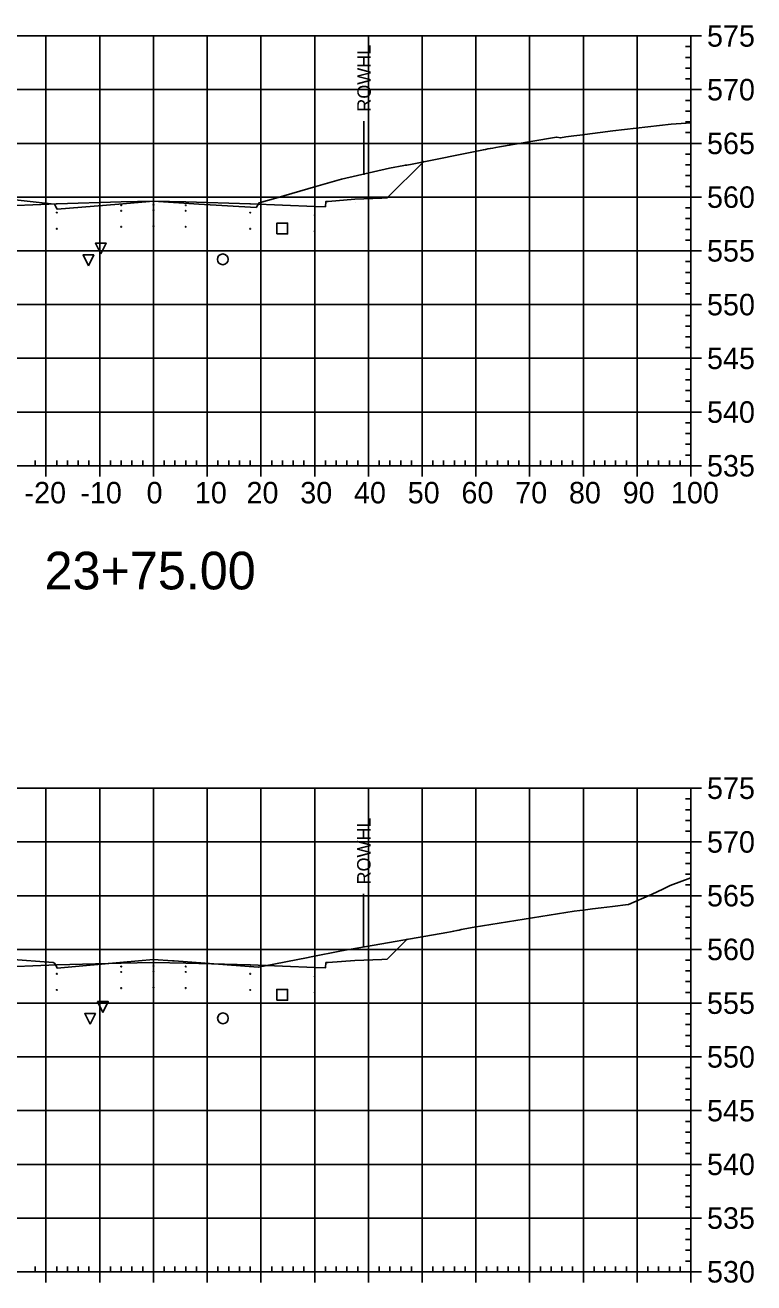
# Model space of a CAD drawing. Extents: x 708103 to 717568, y 374476 to 378707.
# Drawn here: x 709578.1 to 709713.7, y 378082.6 to 378316.6 of the extents above; entities that cross this region are included whole.
import ezdxf

# ---------------------------------------------------------------- set-up
doc = ezdxf.new("R2010")
doc.units = 0
for name, color, linetype in [('1', 7, 'Continuous'), ('13', 7, 'Continuous'), ('14', 7, 'Continuous'), ('22', 7, 'Continuous'), ('4', 7, 'Continuous'), ('57', 7, 'Continuous'), ('Existing', 7, 'Continuous'), ('XS_Right_of_Way', 7, 'Continuous')]:
    doc.layers.add(name, color=color, linetype=linetype)

msp = doc.modelspace()

# ---------------------------------------------------------------- linework, layer by layer
for points in [[(709595.93, 378283.04), (709596.03, 378283.04), (709596.03, 378283.14), (709595.93, 378283.14)], [(709601.93, 378283.16), (709602.03, 378283.16), (709602.03, 378283.26), (709601.93, 378283.26)], [(709607.93, 378283.04), (709608.03, 378283.04), (709608.03, 378283.14), (709607.93, 378283.14)], [(709583.93, 378281.68), (709584.03, 378281.68), (709584.03, 378281.78), (709583.93, 378281.78)], [(709595.93, 378282.04), (709596.03, 378282.04), (709596.03, 378282.14), (709595.93, 378282.14)], [(709601.93, 378282.16), (709602.03, 378282.16), (709602.03, 378282.26), (709601.93, 378282.26)], [(709607.93, 378282.04), (709608.03, 378282.04), (709608.03, 378282.14), (709607.93, 378282.14)], [(709619.93, 378281.68), (709620.03, 378281.68), (709620.03, 378281.78), (709619.93, 378281.78)], [(709631.93, 378281.2), (709632.03, 378281.2), (709632.03, 378281.3), (709631.93, 378281.3)], [(709583.93, 378278.68), (709584.03, 378278.68), (709584.03, 378278.78), (709583.93, 378278.78)], [(709595.93, 378279.04), (709596.03, 378279.04), (709596.03, 378279.14), (709595.93, 378279.14)], [(709601.93, 378279.16), (709602.03, 378279.16), (709602.03, 378279.26), (709601.93, 378279.26)], [(709607.93, 378279.04), (709608.03, 378279.04), (709608.03, 378279.14), (709607.93, 378279.14)], [(709619.93, 378278.68), (709620.03, 378278.68), (709620.03, 378278.78), (709619.93, 378278.78)], [(709631.93, 378278.2), (709632.03, 378278.2), (709632.03, 378278.3), (709631.93, 378278.3)], [(709583.93, 378140.02), (709584.03, 378140.02), (709584.03, 378140.12), (709583.93, 378140.12)], [(709595.93, 378141.38), (709596.03, 378141.38), (709596.03, 378141.48), (709595.93, 378141.48)], [(709595.93, 378140.38), (709596.03, 378140.38), (709596.03, 378140.48), (709595.93, 378140.48)], [(709601.93, 378141.5), (709602.03, 378141.5), (709602.03, 378141.6), (709601.93, 378141.6)], [(709601.93, 378140.5), (709602.03, 378140.5), (709602.03, 378140.6), (709601.93, 378140.6)], [(709607.93, 378141.38), (709608.03, 378141.38), (709608.03, 378141.48), (709607.93, 378141.48)], [(709607.93, 378140.38), (709608.03, 378140.38), (709608.03, 378140.48), (709607.93, 378140.48)], [(709619.93, 378140.02), (709620.03, 378140.02), (709620.03, 378140.12), (709619.93, 378140.12)], [(709595.93, 378137.38), (709596.03, 378137.38), (709596.03, 378137.48), (709595.93, 378137.48)], [(709601.93, 378137.5), (709602.03, 378137.5), (709602.03, 378137.6), (709601.93, 378137.6)], [(709607.93, 378137.38), (709608.03, 378137.38), (709608.03, 378137.48), (709607.93, 378137.48)], [(709631.93, 378139.54), (709632.03, 378139.54), (709632.03, 378139.64), (709631.93, 378139.64)], [(709583.93, 378137.02), (709584.03, 378137.02), (709584.03, 378137.12), (709583.93, 378137.12)], [(709619.93, 378137.02), (709620.03, 378137.02), (709620.03, 378137.12), (709619.93, 378137.12)], [(709631.93, 378136.54), (709632.03, 378136.54), (709632.03, 378136.64), (709631.93, 378136.64)]]:
    msp.add_lwpolyline(points, close=True)
at = {"layer": '1'}
for points in [[(709592.18, 378274.05), (709591.18, 378276.05), (709593.18, 378276.05)], [(709589.88, 378271.87), (709588.88, 378273.87), (709590.88, 378273.87)], [(709592.58, 378132.91), (709591.58, 378134.91), (709593.58, 378134.91)], [(709590.19, 378130.69), (709589.19, 378132.69), (709591.19, 378132.69)]]:
    msp.add_lwpolyline(points, close=True, dxfattribs=at)
at = {"layer": '13'}
for centre in [(709614.88, 378273.05), (709614.91, 378131.81)]:
    msp.add_circle(centre, 1, dxfattribs=at)
at = {"layer": '14'}
for points in [[(709652.22, 378291.21), (709652.22, 378291.26), (709652.22, 378291.21), (709652.17, 378291.21), (709652.22, 378291.21), (709652.22, 378291.16), (709652.22, 378291.21), (709652.27, 378291.21)], [(709583.98, 378283.39), (709583.98, 378283.44), (709583.98, 378283.39), (709583.93, 378283.39), (709583.98, 378283.39), (709583.98, 378283.34), (709583.98, 378283.39), (709584.03, 378283.39)], [(709601.98, 378283.87), (709601.98, 378283.92), (709601.98, 378283.87), (709601.93, 378283.87), (709601.98, 378283.87), (709601.98, 378283.82), (709601.98, 378283.87), (709602.03, 378283.87)], [(709619.98, 378283.39), (709619.98, 378283.44), (709619.98, 378283.39), (709619.93, 378283.39), (709619.98, 378283.39), (709619.98, 378283.34), (709619.98, 378283.39), (709620.03, 378283.39)], [(709631.98, 378282.91), (709631.98, 378282.96), (709631.98, 378282.91), (709631.93, 378282.91), (709631.98, 378282.91), (709631.98, 378282.86), (709631.98, 378282.91), (709632.03, 378282.91)], [(709649.15, 378146.49), (709649.15, 378146.54), (709649.15, 378146.49), (709649.1, 378146.49), (709649.15, 378146.49), (709649.15, 378146.44), (709649.15, 378146.49), (709649.2, 378146.49)], [(709601.98, 378142.22), (709601.98, 378142.27), (709601.98, 378142.22), (709601.93, 378142.22), (709601.98, 378142.22), (709601.98, 378142.17), (709601.98, 378142.22), (709602.03, 378142.22)], [(709583.98, 378141.74), (709583.98, 378141.79), (709583.98, 378141.74), (709583.93, 378141.74), (709583.98, 378141.74), (709583.98, 378141.69), (709583.98, 378141.74), (709584.03, 378141.74)], [(709619.98, 378141.74), (709619.98, 378141.79), (709619.98, 378141.74), (709619.93, 378141.74), (709619.98, 378141.74), (709619.98, 378141.69), (709619.98, 378141.74), (709620.03, 378141.74)], [(709631.98, 378141.26), (709631.98, 378141.31), (709631.98, 378141.26), (709631.93, 378141.26), (709631.98, 378141.26), (709631.98, 378141.21), (709631.98, 378141.26), (709632.03, 378141.26)]]:
    msp.add_lwpolyline(points, dxfattribs=at)
at = {"layer": '22'}
for points in [[(709540.19, 378266.18), (709551.1, 378277.08), (709558.48, 378284.47), (709559.48, 378284.43), (709564.48, 378284.23), (709569.48, 378283.83), (709569.9, 378283.83), (709569.98, 378282.83), (709571.98, 378282.91), (709583.98, 378283.39), (709595.98, 378283.75), (709601.98, 378283.87), (709607.98, 378283.75), (709619.98, 378283.39), (709631.98, 378282.91), (709633.98, 378282.83), (709634.07, 378283.83), (709634.48, 378283.83), (709639.48, 378284.23), (709644.48, 378284.43), (709645.48, 378284.47), (709652.22, 378291.21)], [(709532.6, 378116.93), (709558.48, 378142.82), (709559.48, 378142.78), (709564.48, 378142.58), (709569.48, 378142.18), (709569.9, 378142.18), (709569.98, 378141.18), (709571.98, 378141.26), (709583.98, 378141.74), (709595.98, 378142.1), (709601.98, 378142.22), (709607.98, 378142.1), (709619.98, 378141.74), (709631.98, 378141.26), (709633.98, 378141.18), (709634.07, 378142.18), (709634.48, 378142.18), (709639.48, 378142.58), (709644.48, 378142.78), (709645.48, 378142.82), (709649.15, 378146.49)]]:
    msp.add_lwpolyline(points, dxfattribs=at)
at = {"layer": '4'}
for points in [[(709624.95, 378277.79), (709626.95, 378277.79), (709626.95, 378279.79), (709624.95, 378279.79)], [(709624.93, 378135.18), (709626.93, 378135.18), (709626.93, 378137.18), (709624.93, 378137.18)]]:
    msp.add_lwpolyline(points, close=True, dxfattribs=at)
at = {"layer": '57'}
for p, q in [((709501.98, 378314.63), (709701.98, 378314.63)), ((709581.98, 378234.63), (709581.98, 378314.63)), ((709591.98, 378234.63), (709591.98, 378314.63)), ((709601.98, 378234.63), (709601.98, 378314.63)), ((709611.98, 378234.63), (709611.98, 378314.63)), ((709621.98, 378234.63), (709621.98, 378314.63)), ((709631.98, 378234.63), (709631.98, 378314.63)), ((709641.98, 378234.63), (709641.98, 378314.63)), ((709651.98, 378234.63), (709651.98, 378314.63)), ((709661.98, 378234.63), (709661.98, 378314.63)), ((709671.98, 378234.63), (709671.98, 378314.63)), ((709681.98, 378234.63), (709681.98, 378314.63)), ((709691.98, 378234.63), (709691.98, 378314.63)), ((709701.98, 378234.63), (709701.98, 378314.63)), ((709701.98, 378234.63), (709701.98, 378314.63)), ((709703.98, 378314.63), (709701.98, 378314.63)), ((709701.98, 378312.63), (709700.98, 378312.63)), ((709701.98, 378310.63), (709700.98, 378310.63)), ((709701.98, 378308.63), (709700.98, 378308.63)), ((709701.98, 378306.63), (709700.98, 378306.63)), ((709501.98, 378304.63), (709701.98, 378304.63)), ((709703.98, 378304.63), (709701.98, 378304.63)), ((709701.98, 378302.63), (709700.98, 378302.63)), ((709701.98, 378300.63), (709700.98, 378300.63)), ((709701.98, 378298.63), (709700.98, 378298.63)), ((709701.98, 378296.63), (709700.98, 378296.63)), ((709501.98, 378294.63), (709701.98, 378294.63)), ((709703.98, 378294.63), (709701.98, 378294.63)), ((709701.98, 378292.63), (709700.98, 378292.63)), ((709701.98, 378290.63), (709700.98, 378290.63)), ((709701.98, 378288.63), (709700.98, 378288.63)), ((709701.98, 378286.63), (709700.98, 378286.63)), ((709501.98, 378284.63), (709701.98, 378284.63)), ((709701.98, 378282.63), (709700.98, 378282.63)), ((709703.98, 378284.63), (709701.98, 378284.63)), ((709701.98, 378280.63), (709700.98, 378280.63)), ((709701.98, 378278.63), (709700.98, 378278.63)), ((709701.98, 378276.63), (709700.98, 378276.63)), ((709501.98, 378274.63), (709701.98, 378274.63)), ((709703.98, 378274.63), (709701.98, 378274.63)), ((709701.98, 378272.63), (709700.98, 378272.63)), ((709701.98, 378270.63), (709700.98, 378270.63)), ((709701.98, 378268.63), (709700.98, 378268.63)), ((709701.98, 378266.63), (709700.98, 378266.63)), ((709501.98, 378264.63), (709701.98, 378264.63)), ((709703.98, 378264.63), (709701.98, 378264.63)), ((709701.98, 378262.63), (709700.98, 378262.63)), ((709701.98, 378260.63), (709700.98, 378260.63)), ((709701.98, 378258.63), (709700.98, 378258.63)), ((709501.98, 378254.63), (709701.98, 378254.63)), ((709701.98, 378256.63), (709700.98, 378256.63)), ((709703.98, 378254.63), (709701.98, 378254.63)), ((709701.98, 378252.63), (709700.98, 378252.63)), ((709701.98, 378250.63), (709700.98, 378250.63)), ((709701.98, 378248.63), (709700.98, 378248.63)), ((709701.98, 378246.63), (709700.98, 378246.63)), ((709501.98, 378244.63), (709701.98, 378244.63)), ((709703.98, 378244.63), (709701.98, 378244.63)), ((709701.98, 378242.63), (709700.98, 378242.63)), ((709701.98, 378240.63), (709700.98, 378240.63)), ((709701.98, 378238.63), (709700.98, 378238.63)), ((709701.98, 378236.63), (709700.98, 378236.63)), ((709501.98, 378234.63), (709701.98, 378234.63)), ((709501.98, 378234.63), (709701.98, 378234.63)), ((709579.98, 378234.63), (709579.98, 378235.63)), ((709581.98, 378232.63), (709581.98, 378234.63)), ((709583.98, 378234.63), (709583.98, 378235.63)), ((709585.98, 378234.63), (709585.98, 378235.63)), ((709587.98, 378234.63), (709587.98, 378235.63)), ((709589.98, 378234.63), (709589.98, 378235.63)), ((709591.98, 378232.63), (709591.98, 378234.63)), ((709593.98, 378234.63), (709593.98, 378235.63)), ((709595.98, 378234.63), (709595.98, 378235.63)), ((709597.98, 378234.63), (709597.98, 378235.63)), ((709599.98, 378234.63), (709599.98, 378235.63)), ((709601.98, 378232.63), (709601.98, 378234.63)), ((709603.98, 378234.63), (709603.98, 378235.63)), ((709605.98, 378234.63), (709605.98, 378235.63)), ((709607.98, 378234.63), (709607.98, 378235.63)), ((709609.98, 378234.63), (709609.98, 378235.63)), ((709611.98, 378232.63), (709611.98, 378234.63)), ((709613.98, 378234.63), (709613.98, 378235.63)), ((709615.98, 378234.63), (709615.98, 378235.63)), ((709617.98, 378234.63), (709617.98, 378235.63)), ((709619.98, 378234.63), (709619.98, 378235.63)), ((709621.98, 378232.63), (709621.98, 378234.63)), ((709623.98, 378234.63), (709623.98, 378235.63)), ((709625.98, 378234.63), (709625.98, 378235.63)), ((709627.98, 378234.63), (709627.98, 378235.63)), ((709629.98, 378234.63), (709629.98, 378235.63)), ((709631.98, 378232.63), (709631.98, 378234.63)), ((709633.98, 378234.63), (709633.98, 378235.63)), ((709635.98, 378234.63), (709635.98, 378235.63)), ((709637.98, 378234.63), (709637.98, 378235.63)), ((709639.98, 378234.63), (709639.98, 378235.63)), ((709641.98, 378232.63), (709641.98, 378234.63)), ((709643.98, 378234.63), (709643.98, 378235.63)), ((709645.98, 378234.63), (709645.98, 378235.63)), ((709647.98, 378234.63), (709647.98, 378235.63)), ((709649.98, 378234.63), (709649.98, 378235.63)), ((709651.98, 378232.63), (709651.98, 378234.63)), ((709653.98, 378234.63), (709653.98, 378235.63)), ((709655.98, 378234.63), (709655.98, 378235.63)), ((709657.98, 378234.63), (709657.98, 378235.63)), ((709659.98, 378234.63), (709659.98, 378235.63)), ((709661.98, 378232.63), (709661.98, 378234.63)), ((709663.98, 378234.63), (709663.98, 378235.63)), ((709665.98, 378234.63), (709665.98, 378235.63)), ((709667.98, 378234.63), (709667.98, 378235.63)), ((709669.98, 378234.63), (709669.98, 378235.63)), ((709671.98, 378232.63), (709671.98, 378234.63)), ((709673.98, 378234.63), (709673.98, 378235.63)), ((709675.98, 378234.63), (709675.98, 378235.63)), ((709677.98, 378234.63), (709677.98, 378235.63)), ((709679.98, 378234.63), (709679.98, 378235.63)), ((709681.98, 378232.63), (709681.98, 378234.63)), ((709683.98, 378234.63), (709683.98, 378235.63)), ((709685.98, 378234.63), (709685.98, 378235.63)), ((709687.98, 378234.63), (709687.98, 378235.63)), ((709689.98, 378234.63), (709689.98, 378235.63)), ((709691.98, 378232.63), (709691.98, 378234.63)), ((709693.98, 378234.63), (709693.98, 378235.63)), ((709695.98, 378234.63), (709695.98, 378235.63)), ((709697.98, 378234.63), (709697.98, 378235.63)), ((709699.98, 378234.63), (709699.98, 378235.63)), ((709701.98, 378232.63), (709701.98, 378234.63)), ((709703.98, 378234.63), (709701.98, 378234.63)), ((709501.98, 378174.63), (709701.98, 378174.63)), ((709581.98, 378084.63), (709581.98, 378174.63)), ((709591.98, 378084.63), (709591.98, 378174.63)), ((709601.98, 378084.63), (709601.98, 378174.63)), ((709611.98, 378084.63), (709611.98, 378174.63)), ((709621.98, 378084.63), (709621.98, 378174.63)), ((709631.98, 378084.63), (709631.98, 378174.63)), ((709641.98, 378084.63), (709641.98, 378174.63)), ((709651.98, 378084.63), (709651.98, 378174.63)), ((709661.98, 378084.63), (709661.98, 378174.63)), ((709671.98, 378084.63), (709671.98, 378174.63)), ((709681.98, 378084.63), (709681.98, 378174.63)), ((709691.98, 378084.63), (709691.98, 378174.63)), ((709701.98, 378172.63), (709700.98, 378172.63)), ((709701.98, 378084.63), (709701.98, 378174.63)), ((709701.98, 378084.63), (709701.98, 378174.63)), ((709703.98, 378174.63), (709701.98, 378174.63)), ((709701.98, 378170.63), (709700.98, 378170.63)), ((709701.98, 378168.63), (709700.98, 378168.63)), ((709701.98, 378166.63), (709700.98, 378166.63)), ((709501.98, 378164.63), (709701.98, 378164.63)), ((709703.98, 378164.63), (709701.98, 378164.63)), ((709701.98, 378162.63), (709700.98, 378162.63)), ((709701.98, 378160.63), (709700.98, 378160.63)), ((709701.98, 378158.63), (709700.98, 378158.63)), ((709701.98, 378156.63), (709700.98, 378156.63)), ((709501.98, 378154.63), (709701.98, 378154.63)), ((709703.98, 378154.63), (709701.98, 378154.63)), ((709701.98, 378152.63), (709700.98, 378152.63)), ((709701.98, 378150.63), (709700.98, 378150.63)), ((709701.98, 378148.63), (709700.98, 378148.63)), ((709501.98, 378144.63), (709701.98, 378144.63)), ((709701.98, 378146.63), (709700.98, 378146.63)), ((709703.98, 378144.63), (709701.98, 378144.63)), ((709701.98, 378142.63), (709700.98, 378142.63)), ((709701.98, 378140.63), (709700.98, 378140.63)), ((709701.98, 378138.63), (709700.98, 378138.63)), ((709701.98, 378136.63), (709700.98, 378136.63)), ((709501.98, 378134.63), (709701.98, 378134.63)), ((709703.98, 378134.63), (709701.98, 378134.63)), ((709701.98, 378132.63), (709700.98, 378132.63)), ((709701.98, 378130.63), (709700.98, 378130.63)), ((709701.98, 378128.63), (709700.98, 378128.63)), ((709701.98, 378126.63), (709700.98, 378126.63)), ((709501.98, 378124.63), (709701.98, 378124.63)), ((709703.98, 378124.63), (709701.98, 378124.63)), ((709701.98, 378122.63), (709700.98, 378122.63)), ((709701.98, 378120.63), (709700.98, 378120.63)), ((709701.98, 378118.63), (709700.98, 378118.63)), ((709701.98, 378116.63), (709700.98, 378116.63)), ((709501.98, 378114.63), (709701.98, 378114.63)), ((709703.98, 378114.63), (709701.98, 378114.63)), ((709701.98, 378112.63), (709700.98, 378112.63)), ((709701.98, 378110.63), (709700.98, 378110.63)), ((709701.98, 378108.63), (709700.98, 378108.63)), ((709701.98, 378106.63), (709700.98, 378106.63)), ((709501.98, 378104.63), (709701.98, 378104.63)), ((709701.98, 378102.63), (709700.98, 378102.63)), ((709703.98, 378104.63), (709701.98, 378104.63)), ((709701.98, 378100.63), (709700.98, 378100.63)), ((709701.98, 378098.63), (709700.98, 378098.63)), ((709701.98, 378096.63), (709700.98, 378096.63)), ((709501.98, 378094.63), (709701.98, 378094.63)), ((709703.98, 378094.63), (709701.98, 378094.63)), ((709701.98, 378092.63), (709700.98, 378092.63)), ((709701.98, 378090.63), (709700.98, 378090.63)), ((709701.98, 378088.63), (709700.98, 378088.63)), ((709701.98, 378086.63), (709700.98, 378086.63)), ((709501.98, 378084.63), (709701.98, 378084.63)), ((709501.98, 378084.63), (709701.98, 378084.63)), ((709579.98, 378084.63), (709579.98, 378085.63)), ((709581.98, 378082.63), (709581.98, 378084.63)), ((709583.98, 378084.63), (709583.98, 378085.63)), ((709585.98, 378084.63), (709585.98, 378085.63)), ((709587.98, 378084.63), (709587.98, 378085.63)), ((709589.98, 378084.63), (709589.98, 378085.63)), ((709591.98, 378082.63), (709591.98, 378084.63)), ((709593.98, 378084.63), (709593.98, 378085.63)), ((709595.98, 378084.63), (709595.98, 378085.63)), ((709597.98, 378084.63), (709597.98, 378085.63)), ((709599.98, 378084.63), (709599.98, 378085.63)), ((709601.98, 378082.63), (709601.98, 378084.63)), ((709603.98, 378084.63), (709603.98, 378085.63)), ((709605.98, 378084.63), (709605.98, 378085.63)), ((709607.98, 378084.63), (709607.98, 378085.63)), ((709609.98, 378084.63), (709609.98, 378085.63)), ((709611.98, 378082.63), (709611.98, 378084.63)), ((709613.98, 378084.63), (709613.98, 378085.63)), ((709615.98, 378084.63), (709615.98, 378085.63)), ((709617.98, 378084.63), (709617.98, 378085.63)), ((709619.98, 378084.63), (709619.98, 378085.63)), ((709621.98, 378082.63), (709621.98, 378084.63)), ((709623.98, 378084.63), (709623.98, 378085.63)), ((709625.98, 378084.63), (709625.98, 378085.63)), ((709627.98, 378084.63), (709627.98, 378085.63)), ((709629.98, 378084.63), (709629.98, 378085.63)), ((709631.98, 378082.63), (709631.98, 378084.63)), ((709633.98, 378084.63), (709633.98, 378085.63)), ((709635.98, 378084.63), (709635.98, 378085.63)), ((709637.98, 378084.63), (709637.98, 378085.63)), ((709639.98, 378084.63), (709639.98, 378085.63)), ((709641.98, 378082.63), (709641.98, 378084.63)), ((709643.98, 378084.63), (709643.98, 378085.63)), ((709645.98, 378084.63), (709645.98, 378085.63)), ((709647.98, 378084.63), (709647.98, 378085.63)), ((709649.98, 378084.63), (709649.98, 378085.63)), ((709651.98, 378082.63), (709651.98, 378084.63)), ((709653.98, 378084.63), (709653.98, 378085.63)), ((709655.98, 378084.63), (709655.98, 378085.63)), ((709657.98, 378084.63), (709657.98, 378085.63)), ((709659.98, 378084.63), (709659.98, 378085.63)), ((709661.98, 378082.63), (709661.98, 378084.63)), ((709663.98, 378084.63), (709663.98, 378085.63)), ((709665.98, 378084.63), (709665.98, 378085.63)), ((709667.98, 378084.63), (709667.98, 378085.63)), ((709669.98, 378084.63), (709669.98, 378085.63)), ((709671.98, 378082.63), (709671.98, 378084.63)), ((709673.98, 378084.63), (709673.98, 378085.63)), ((709675.98, 378084.63), (709675.98, 378085.63)), ((709677.98, 378084.63), (709677.98, 378085.63)), ((709679.98, 378084.63), (709679.98, 378085.63)), ((709681.98, 378082.63), (709681.98, 378084.63)), ((709683.98, 378084.63), (709683.98, 378085.63)), ((709685.98, 378084.63), (709685.98, 378085.63)), ((709687.98, 378084.63), (709687.98, 378085.63)), ((709689.98, 378084.63), (709689.98, 378085.63)), ((709691.98, 378082.63), (709691.98, 378084.63)), ((709693.98, 378084.63), (709693.98, 378085.63)), ((709695.98, 378084.63), (709695.98, 378085.63)), ((709697.98, 378084.63), (709697.98, 378085.63)), ((709699.98, 378084.63), (709699.98, 378085.63)), ((709701.98, 378082.63), (709701.98, 378084.63)), ((709703.98, 378084.63), (709701.98, 378084.63))]:
    msp.add_line(p, q, dxfattribs=at)
at = {"layer": 'Existing'}
for points in [[(709576.24, 378284.14), (709582.95, 378283.38), (709583.55, 378283.32), (709583.79, 378282.85), (709584.03, 378282.39), (709595.55, 378283.33), (709601.98, 378283.88), (709610.4, 378283.31), (709621.09, 378282.68), (709621.15, 378282.77), (709621.63, 378283.55), (709624.73, 378284.44), (709632.19, 378286.61), (709636.95, 378287.96), (709645.89, 378290), (709648.55, 378290.49), (709648.84, 378290.55), (709649.14, 378290.6), (709650.13, 378290.79), (709663.37, 378293.44), (709663.78, 378293.51), (709664.21, 378293.59), (709664.66, 378293.67), (709665.16, 378293.76), (709665.71, 378293.86), (709666.35, 378293.97), (709667.14, 378294.11), (709668.2, 378294.29), (709669.67, 378294.54), (709672.18, 378294.96), (709676.96, 378295.77), (709677.03, 378295.76), (709677.74, 378295.65), (709678.71, 378295.84), (709680.19, 378296.02), (709681.34, 378296.14), (709687.44, 378296.97), (709698.31, 378298.21), (709701.13, 378298.4), (709701.98, 378298.46)], [(709575.09, 378142.83), (709583.32, 378142.18), (709583.55, 378142.09), (709583.98, 378141.32), (709584.07, 378141.12), (709596.41, 378142.27), (709601.98, 378142.75), (709605.5, 378142.51), (709605.82, 378142.49), (709621.49, 378141.31), (709621.78, 378141.39), (709622.44, 378141.5), (709630.74, 378143.13), (709631.03, 378143.19), (709637.29, 378144.41), (709638.77, 378144.7), (709656.54, 378147.76), (709657.23, 378147.9), (709657.87, 378148.03), (709658.44, 378148.14), (709658.89, 378148.24), (709659.08, 378148.28), (709659.24, 378148.31), (709661.66, 378148.74), (709680.24, 378151.76), (709682.37, 378152.01), (709683.69, 378152.16), (709685.29, 378152.36), (709687.39, 378152.61), (709690.32, 378152.97), (709690.4, 378153), (709694.67, 378154.87), (709696.89, 378155.9), (709698.15, 378156.54), (709701.98, 378157.92)]]:
    msp.add_lwpolyline(points, dxfattribs=at)
at = {"layer": 'XS_Right_of_Way'}
for p, q in [((709641.1, 378298.77), (709641.1, 378288.77)), ((709641.06, 378154.96), (709641.06, 378144.96))]:
    msp.add_line(p, q, dxfattribs=at)

# ---------------------------------------------------------------- texts
at = {"layer": '1'}
msp.add_text('23+75.00', height=7, dxfattribs=at).set_placement((709581.71, 378211.63))
at = {"layer": '14'}
for p in [(709639.45, 378283.52), (709644.45, 378284.38), (709644.45, 378283.72), (709644.45, 378142.73), (709644.45, 378142.06), (709639.45, 378141.86)]:
    msp.add_text('+', height=0.1, dxfattribs=at).set_placement(p)
at = {"layer": '57'}
for s, p in [('575', (709704.98, 378312.63)), ('570', (709704.98, 378302.63)), ('565', (709704.98, 378292.63)), ('560', (709704.98, 378282.63)), ('555', (709704.98, 378272.63)), ('550', (709704.98, 378262.63)), ('545', (709704.98, 378252.63)), ('540', (709704.98, 378242.63)), ('535', (709704.98, 378232.63)), ('-20', (709577.98, 378227.63)), ('-10', (709588.37, 378227.63)), ('0', (709600.69, 378227.63)), ('10', (709609.68, 378227.63)), ('20', (709619.29, 378227.63)), ('30', (709629.29, 378227.63)), ('40', (709639.29, 378227.63)), ('50', (709649.29, 378227.63)), ('60', (709659.29, 378227.63)), ('70', (709669.29, 378227.63)), ('80', (709679.29, 378227.63)), ('90', (709689.29, 378227.63)), ('100', (709698.28, 378227.63)), ('575', (709704.98, 378172.63)), ('570', (709704.98, 378162.63)), ('565', (709704.98, 378152.63)), ('560', (709704.98, 378142.63)), ('555', (709704.98, 378132.63)), ('550', (709704.98, 378122.63)), ('545', (709704.98, 378112.63)), ('540', (709704.98, 378102.63)), ('535', (709704.98, 378092.63)), ('530', (709704.98, 378082.63))]:
    msp.add_text(s, height=4, dxfattribs=at).set_placement(p)
at = {"layer": 'XS_Right_of_Way'}
for p in [(709642.42, 378300.53), (709642.38, 378156.72)]:
    msp.add_text('ROWHL', height=2.5, rotation=90, dxfattribs=at).set_placement(p)

doc.saveas('drawing.dxf')
